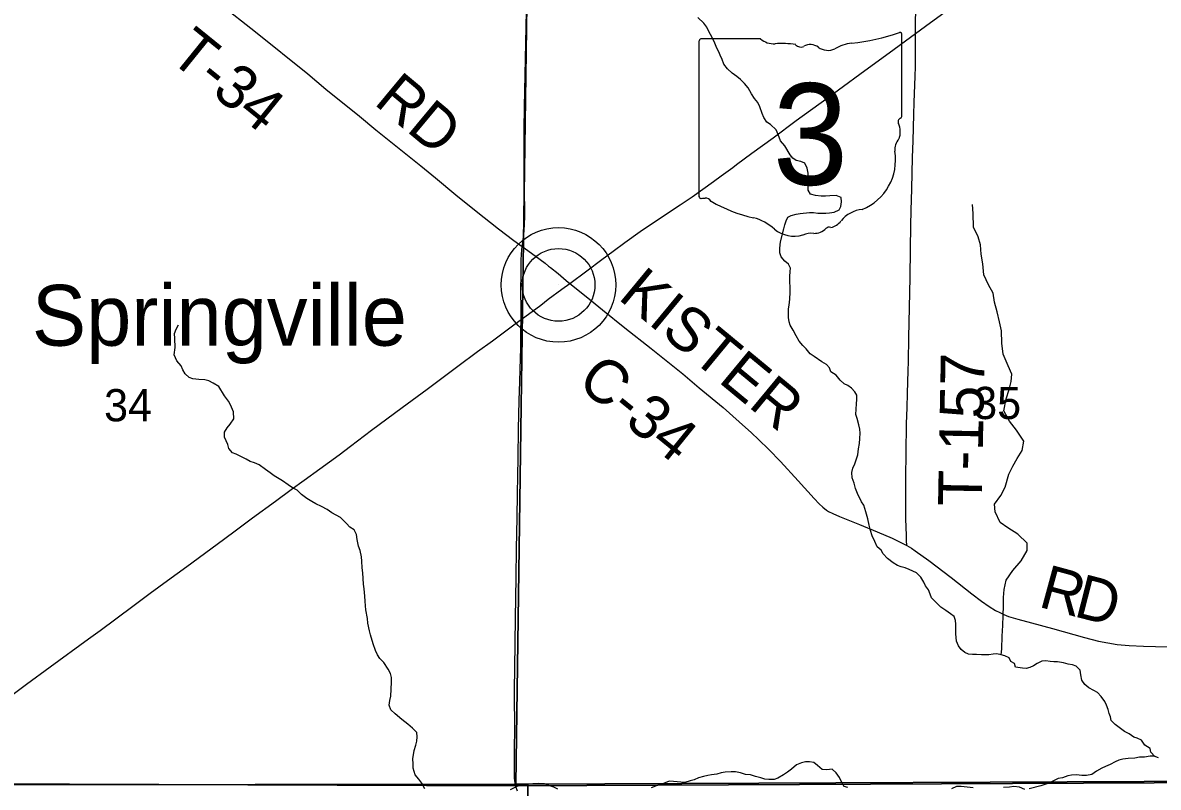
# Model space of a CAD drawing. Extents: x 0 to 34, y 0 to 22.
# Drawn here: x 2.961 to 4.435, y 15.868 to 16.861 of the extents above; entities that cross this region are included whole.
import ezdxf

# ---------------------------------------------------------------- set-up
doc = ezdxf.new("R2010")
doc.units = 0
for name, color, linetype in [('GM_X_County_Road', 7, 'Continuous'), ('GM_X_County_Road_Text', 7, 'Continuous'), ('GM_X_Minor_River', 7, 'Continuous'), ('GM_X_Section', 7, 'Continuous'), ('GM_X_Section_Text', 7, 'Continuous'), ('GM_X_State_Location', 7, 'Continuous'), ('GM_X_State_Route', 7, 'Continuous'), ('GM_X_State_Shield', 7, 'Continuous'), ('GM_X_Township_Road', 7, 'Continuous'), ('GM_X_Township_Road_Text', 7, 'Continuous'), ('GM_X_Unincorporated', 7, 'Continuous'), ('GM_X_Unincorporated_Location', 7, 'Continuous'), ('GM_X_Unincorporated_Text', 7, 'Continuous')]:
    doc.layers.add(name, color=color, linetype=linetype)

msp = doc.modelspace()

# ---------------------------------------------------------------- linework, layer by layer
at = {"layer": 'GM_X_County_Road'}
for points in [[(4.1202, 16.8475), (4.1206, 16.8925)], [(3.6712, 16.5229), (3.6752, 16.5197), (3.6994, 16.5003), (3.7139, 16.4886), (3.7428, 16.4651), (3.777, 16.4382), (3.7987, 16.4209), (3.8179, 16.4053), (3.8394, 16.3874), (3.8703, 16.3616), (3.8912, 16.3431), (3.9074, 16.3286), (3.9165, 16.3201), (3.9297, 16.3071), (3.9448, 16.2915), (3.968, 16.2665), (3.9887, 16.2433), (3.995, 16.2364), (3.9997, 16.2322), (4.0047, 16.2284), (4.0073, 16.2267), (4.0129, 16.2238), (4.0214, 16.22), (4.0473, 16.2095), (4.0703, 16.2003), (4.0898, 16.1918), (4.0949, 16.1895), (4.101, 16.1864), (4.108, 16.1827), (4.109, 16.1822)], [(4.109, 16.1822), (4.1148, 16.179), (4.1199, 16.1755), (4.1373, 16.1631), (4.1666, 16.1407), (4.1935, 16.1197), (4.2058, 16.1102), (4.2159, 16.103), (4.2239, 16.0981), (4.2295, 16.0952), (4.2351, 16.0926), (4.241, 16.0904), (4.2529, 16.0868), (4.2709, 16.0819), (4.2979, 16.0748), (4.3398, 16.0631), (4.3578, 16.0583), (4.37, 16.0558), (4.3823, 16.054), (4.3978, 16.0526), (4.4165, 16.0517), (4.4476, 16.0509)]]:
    msp.add_lwpolyline(points, dxfattribs=at)
at = {"layer": 'GM_X_Minor_River'}
for points in [[(3.8691, 16.8135), (3.8665, 16.8192), (3.8649, 16.8237), (3.8622, 16.8283), (3.8595, 16.8348), (3.8561, 16.8424), (3.8519, 16.85), (3.8492, 16.8557), (3.8454, 16.8606), (3.8373, 16.8682)], [(4.0463, 16.308), (4.0474, 16.3148), (4.0481, 16.3213), (4.0485, 16.3281), (4.0481, 16.3335), (4.0466, 16.3392), (4.0446, 16.3475), (4.0427, 16.3525), (4.0431, 16.3597), (4.0435, 16.3662), (4.0442, 16.3719), (4.0442, 16.3776), (4.0415, 16.3821), (4.0369, 16.3867), (4.0323, 16.3901), (4.0274, 16.3924), (4.0224, 16.397), (4.017, 16.4035), (4.0102, 16.408), (4.0086, 16.413), (4.0044, 16.4175), (3.9987, 16.421), (3.9884, 16.4278), (3.9834, 16.4312), (3.9784, 16.4377), (3.9738, 16.4423), (3.9692, 16.448), (3.965, 16.4548), (3.9612, 16.462), (3.9574, 16.4685), (3.9562, 16.4731), (3.9554, 16.4784), (3.9554, 16.4852), (3.9554, 16.4898), (3.9561, 16.4947), (3.9569, 16.5024), (3.9576, 16.5115), (3.9572, 16.5187), (3.9568, 16.524), (3.9568, 16.532), (3.9576, 16.5381), (3.9579, 16.5427), (3.9553, 16.548), (3.9503, 16.5518), (3.9457, 16.5575), (3.9438, 16.5624), (3.9438, 16.5685), (3.9449, 16.5769), (3.949, 16.5936), (3.9506, 16.5989), (3.9521, 16.6039), (3.9543, 16.6088), (3.9589, 16.6111), (3.965, 16.6126), (3.9704, 16.6134), (3.9826, 16.6149), (3.9875, 16.6149), (3.9933, 16.6141), (4.0039, 16.6141), (4.0085, 16.6145), (4.0146, 16.6153), (4.0211, 16.6183), (4.0234, 16.6229), (4.0241, 16.6286), (4.0237, 16.6343), (4.0172, 16.6369), (4.0089, 16.6366), (4.0035, 16.6362), (3.9978, 16.6362), (3.9902, 16.6369), (3.984, 16.6389), (3.981, 16.6438), (3.981, 16.6548), (3.9809, 16.6617), (3.9809, 16.6662), (3.9794, 16.6727), (3.9763, 16.6792), (3.9713, 16.6811), (3.9652, 16.6826), (3.9607, 16.6853), (3.9572, 16.6898), (3.9507, 16.7016), (3.945, 16.7081), (3.9419, 16.7164), (3.9392, 16.7222), (3.9319, 16.729), (3.9273, 16.7321), (3.9231, 16.7381), (3.9212, 16.7435), (3.9181, 16.7522), (3.9154, 16.7579), (3.9109, 16.7629), (3.9074, 16.7689), (3.9028, 16.7769), (3.8982, 16.7823), (3.8929, 16.7876), (3.8883, 16.7914), (3.8822, 16.796), (3.876, 16.8017), (3.8714, 16.8074), (3.8691, 16.8135)], [(4.2314, 16.0406), (4.2325, 16.0484), (4.2329, 16.0647), (4.2336, 16.0784), (4.2339, 16.0917), (4.2346, 16.1042), (4.2346, 16.1148), (4.2353, 16.1251), (4.2379, 16.1376), (4.2466, 16.1498), (4.2575, 16.1627), (4.2654, 16.176), (4.2654, 16.1855), (4.2532, 16.1972), (4.2403, 16.2052), (4.23, 16.2123), (4.2235, 16.226), (4.2227, 16.2359), (4.231, 16.2473), (4.2367, 16.2583), (4.2415, 16.275), (4.2464, 16.2853), (4.2524, 16.2955), (4.2588, 16.3058), (4.2607, 16.318), (4.2512, 16.3324), (4.2424, 16.3441), (4.2348, 16.3573), (4.2381, 16.3729), (4.2419, 16.3851), (4.2445, 16.3953), (4.2452, 16.4048), (4.2406, 16.4158), (4.2341, 16.431), (4.2325, 16.445), (4.2317, 16.4613), (4.2294, 16.4727), (4.2263, 16.486), (4.2229, 16.4985), (4.2209, 16.5103), (4.2152, 16.5209), (4.2091, 16.5341), (4.2075, 16.5482), (4.2056, 16.5607), (4.2044, 16.5728), (4.2017, 16.5831), (4.1956, 16.5959), (4.1952, 16.6138), (4.194, 16.6255)], [(3.469, 15.9163), (3.4713, 15.9231), (3.4724, 15.9284), (3.4732, 15.9338), (3.4724, 15.9395), (3.4671, 15.9452), (3.4609, 15.9505), (3.4529, 15.9566), (3.4445, 15.9638), (3.4388, 15.9691), (3.4368, 15.9752), (3.4376, 15.9809), (3.4387, 15.9866), (3.4398, 16.0049), (3.4398, 16.011), (3.4383, 16.0163), (3.4352, 16.0216), (3.4295, 16.0304), (3.4245, 16.0357), (3.4214, 16.0406), (3.4187, 16.046), (3.4157, 16.0547), (3.4126, 16.0665), (3.411, 16.0718), (3.4091, 16.0817), (3.4083, 16.0874), (3.4064, 16.0988), (3.406, 16.1041), (3.4056, 16.1102), (3.4052, 16.1167), (3.404, 16.1262), (3.4033, 16.1323), (3.4025, 16.1467), (3.4017, 16.1536), (3.4013, 16.1619), (3.4005, 16.1677), (3.399, 16.176), (3.3967, 16.1817), (3.3951, 16.1901), (3.3943, 16.1969), (3.3913, 16.2026), (3.3855, 16.2061), (3.3813, 16.211), (3.3733, 16.2186), (3.3679, 16.222), (3.3622, 16.2247), (3.3561, 16.2293), (3.3488, 16.2331), (3.3412, 16.2365), (3.3362, 16.2396), (3.3297, 16.2434), (3.3228, 16.2487), (3.3171, 16.2544), (3.311, 16.2574), (3.3053, 16.2612), (3.298, 16.2666), (3.2873, 16.2727), (3.2819, 16.2769), (3.2762, 16.281), (3.2678, 16.2871), (3.2617, 16.2898), (3.256, 16.2913), (3.251, 16.2944), (3.238, 16.3012), (3.233, 16.3027), (3.2284, 16.3084), (3.2269, 16.3138), (3.2227, 16.3233), (3.2227, 16.3294), (3.2261, 16.3351), (3.2303, 16.34), (3.2348, 16.3468), (3.2344, 16.356), (3.2306, 16.3651), (3.2279, 16.37), (3.2229, 16.3769), (3.2153, 16.3891), (3.208, 16.3933), (3.2023, 16.3963), (3.1973, 16.3974), (3.1893, 16.3982), (3.1817, 16.399), (3.1767, 16.4005), (3.1717, 16.4054), (3.1687, 16.4104), (3.1664, 16.4157), (3.161, 16.4222), (3.1575, 16.4302), (3.1587, 16.4397), (3.1583, 16.4511), (3.1579, 16.4579), (3.1598, 16.4633), (3.1632, 16.469)], [(4.4309, 15.9085), (4.4258, 15.9138), (4.425, 15.9188), (4.4181, 15.9233), (4.4139, 15.9294), (4.4082, 15.9321), (4.4036, 15.9336), (4.3975, 15.9378), (4.3914, 15.9408), (4.3845, 15.9462), (4.3795, 15.95), (4.3745, 15.9553), (4.3734, 15.9599), (4.3715, 15.9644), (4.3703, 15.9694), (4.3684, 15.9751), (4.3661, 15.9796), (4.3611, 15.9861), (4.3565, 15.9914), (4.3516, 15.9941), (4.3454, 15.9975), (4.3401, 16.0017), (4.3363, 16.0074), (4.3347, 16.0146), (4.3339, 16.0204), (4.329, 16.0257), (4.324, 16.0276), (4.3183, 16.0283), (4.3125, 16.0299), (4.3045, 16.0314), (4.2999, 16.0314), (4.295, 16.0318), (4.2893, 16.0325), (4.2843, 16.0322), (4.2782, 16.0291), (4.2736, 16.0261), (4.2687, 16.0238), (4.2641, 16.0227), (4.2591, 16.0231), (4.25, 16.0246), (4.2488, 16.0291), (4.2442, 16.0318), (4.2419, 16.0364), (4.2362, 16.039), (4.2316, 16.0406), (4.2259, 16.0417), (4.2209, 16.0413), (4.2156, 16.0406), (4.2106, 16.0402), (4.206, 16.0402), (4.1992, 16.041), (4.1942, 16.041), (4.1892, 16.0413), (4.1843, 16.0433), (4.1797, 16.0474), (4.1762, 16.052), (4.1736, 16.0581), (4.1728, 16.063), (4.1724, 16.0676), (4.1724, 16.0741), (4.1724, 16.0801), (4.172, 16.0851), (4.1704, 16.09), (4.1658, 16.0938), (4.1597, 16.098), (4.1532, 16.1022), (4.141, 16.1144), (4.1391, 16.1193), (4.1372, 16.1247), (4.1333, 16.13), (4.131, 16.1349), (4.1272, 16.1414), (4.1215, 16.1471), (4.1169, 16.149), (4.1119, 16.1513), (4.1066, 16.1536), (4.1016, 16.1547), (4.0966, 16.1566), (4.0913, 16.16), (4.084, 16.1657), (4.0783, 16.1715), (4.0756, 16.1764), (4.0706, 16.1806), (4.0675, 16.1878), (4.0641, 16.195), (4.0618, 16.2019), (4.0602, 16.2087), (4.0583, 16.2171), (4.0556, 16.2262), (4.0529, 16.2346), (4.0502, 16.2392), (4.0449, 16.2498), (4.0422, 16.2563), (4.0407, 16.2635), (4.038, 16.2703), (4.0376, 16.2772), (4.0387, 16.2829), (4.0414, 16.2886), (4.0436, 16.2951), (4.0451, 16.3), (4.0463, 16.308)], [(3.4829, 15.8664), (3.4791, 15.8737), (3.4752, 15.879), (3.4703, 15.8847), (3.4679, 15.8934), (3.4679, 15.8988), (3.4675, 15.9052), (3.469, 15.9163)], [(4.0324, 15.868), (4.0275, 15.8696), (4.024, 15.8756), (4.0213, 15.8813), (4.0171, 15.8871), (4.0121, 15.892), (4.0049, 15.8909), (3.9988, 15.8916), (3.9931, 15.8966), (3.9881, 15.9004), (3.9827, 15.9015), (3.9774, 15.9015), (3.9721, 15.9), (3.9656, 15.8974), (3.9591, 15.892), (3.9541, 15.8882), (3.9488, 15.8844), (3.9416, 15.8803), (3.9366, 15.8787), (3.9297, 15.8784), (3.9244, 15.8791), (3.9194, 15.8806), (3.9122, 15.8822), (3.9057, 15.8845), (3.8992, 15.8852), (3.8931, 15.8871), (3.8866, 15.8883), (3.8809, 15.8883), (3.8729, 15.8879), (3.8679, 15.8871), (3.8622, 15.8856), (3.8553, 15.8845), (3.8504, 15.8837), (3.845, 15.8822), (3.8385, 15.8807), (3.8328, 15.878), (3.8275, 15.8769), (3.8206, 15.8746), (3.8153, 15.875), (3.8061, 15.8761), (3.8004, 15.8765), (3.7928, 15.8731), (3.7847, 15.8705), (3.7771, 15.8678)], [(4.4357, 15.9066), (4.43, 15.9089), (4.425, 15.9089), (4.4178, 15.9077), (4.4109, 15.9074), (4.4052, 15.9062), (4.3964, 15.9059), (4.3895, 15.9051), (4.3842, 15.9036), (4.3793, 15.9013), (4.3732, 15.8979), (4.3671, 15.8952), (4.3621, 15.8933), (4.3552, 15.8895), (4.3491, 15.885), (4.3423, 15.8838), (4.3362, 15.8835), (4.3293, 15.8846), (4.3228, 15.8842), (4.3179, 15.8831), (4.311, 15.8808), (4.3053, 15.8797), (4.2969, 15.8755), (4.2908, 15.8728), (4.2828, 15.8702), (4.2679, 15.8664)], [(3.6558, 15.866), (3.6504, 15.8686), (3.6439, 15.8705), (3.6382, 15.8728), (3.6302, 15.8732), (3.6233, 15.8728), (3.6145, 15.8721), (3.6092, 15.8713), (3.6023, 15.8694), (3.5939, 15.8649)], [(4.195, 15.8676), (4.1874, 15.8687), (4.1797, 15.8695), (4.1736, 15.8695), (4.1668, 15.8664)], [(4.2622, 15.8656), (4.2553, 15.8687), (4.2477, 15.8694), (4.2423, 15.8687), (4.2343, 15.8683)]]:
    msp.add_lwpolyline(points, dxfattribs=at)
at = {"layer": 'GM_X_Section'}
for points in [[(2.5888, 16.8843), (3.6155, 16.8848), (3.6011, 15.8725), (2.5857, 15.8713)], [(3.6155, 16.8848), (4.6282, 16.8848), (4.6171, 15.8766), (3.6166, 15.8725), (3.6011, 15.8725)], [(3.6011, 15.8725), (3.6166, 15.8725), (3.6188, 14.8751), (2.6012, 14.88), (2.5857, 15.8713)], [(3.6166, 15.8725), (4.6171, 15.8766), (4.6247, 14.8633), (4.1707, 14.8603), (3.6188, 14.8751)]]:
    msp.add_lwpolyline(points, close=True, dxfattribs=at)
at = {"layer": 'GM_X_State_Route'}
for points in [[(2.1, 20.9), (2.1, 15.8695), (2.5819, 15.8726), (2.7891, 15.8734), (3.6011, 15.8701), (4.6144, 15.8751)], [(2.931, 15.9768), (2.9657, 16.0025), (2.9965, 16.0249), (3.0463, 16.0612), (3.0613, 16.0722), (3.1036, 16.1037), (3.1262, 16.1203), (3.1487, 16.1368), (3.1738, 16.1552), (3.2214, 16.19), (3.2383, 16.2029), (3.2593, 16.2184), (3.2891, 16.2398), (3.3095, 16.2551), (3.3264, 16.2673), (3.3466, 16.2819), (3.3715, 16.3003), (3.3863, 16.3116), (3.4138, 16.332), (3.4537, 16.3616), (3.4862, 16.3856), (3.5258, 16.4152), (3.5515, 16.4343), (3.5707, 16.4484), (3.6001, 16.4704), (3.6079, 16.4761), (3.6334, 16.4947), (3.6433, 16.5022), (3.6607, 16.5152), (3.6712, 16.5229), (3.6932, 16.539), (3.7128, 16.5538), (3.7276, 16.5646), (3.7427, 16.576), (3.7626, 16.5903), (3.793, 16.6105), (3.8147, 16.6247), (3.83, 16.6352), (3.8577, 16.6551), (3.8678, 16.6625), (3.8828, 16.6735), (3.8878, 16.6772), (3.9078, 16.6919), (3.9353, 16.7121), (3.9654, 16.7342), (4.0055, 16.7635), (4.0478, 16.7945), (4.0925, 16.8272), (4.1139, 16.8428), (4.1202, 16.8475), (4.1333, 16.8569), (4.1635, 16.8788)], [(4.6144, 15.8751), (3.6011, 15.8701), (2.7891, 15.8734), (2.5819, 15.8726), (2.1, 15.8695), (2.1, 14.1), (5.6455, 14.1)]]:
    msp.add_lwpolyline(points, dxfattribs=at)
at = {"layer": 'GM_X_State_Shield'}
for p, q in [((4.1026, 16.7406), (4.1026, 16.8453)), ((3.839, 16.8369), (3.839, 16.6368)), ((3.9188, 16.8403), (3.8416, 16.8403)), ((4.1026, 16.7406), (4.1026, 16.7406))]:
    msp.add_line(p, q, dxfattribs=at)
for centre, radius, start, end in [((4.0087, 17.1131), 0.2796, 275.8445, 288.9065), ((4.0997, 16.8457), 0.00294, 351.8621, 97.738), ((3.842, 16.8373), 0.00305, 98.1301, 188.1301), ((3.9372, 16.8635), 0.0296, 231.6195, 271.1119), ((3.947, 16.728), 0.1064, 80.4867, 94.9883), ((3.9711, 16.8383), 0.00855, 219.7921, 297.1024), ((3.9837, 16.8152), 0.0178, 54.4667, 119.1411), ((4.0066, 16.8469), 0.0214, 233.8562, 294.8282), ((4.0444, 16.7792), 0.0563, 97.3462, 120.7689), ((4.0995, 16.7402), 0.00314, 289.6038, 7.7341), ((4.102, 16.7329), 0.00454, 107.944, 210.337), ((4.0731, 16.7197), 0.0273, 340.033, 23.6496), ((4.1131, 16.6968), 0.0198, 136.8065, 186.9296), ((4.0244, 16.6835), 0.0699, 292.3089, 8.9858), ((3.842, 16.6363), 0.00308, 171.9584, 258.3066), ((3.8425, 16.6568), 0.0235, 267.339, 280.6039), ((3.8473, 16.6252), 0.00848, 29.7484, 93.2717), ((3.9544, 16.805), 0.2019, 240.4129, 257.1985), ((3.8942, 16.5468), 0.0632, 47.1842, 75.836), ((4.0539, 16.5806), 0.0383, 94.4031, 142.5768), ((3.9625, 16.6242), 0.0401, 230.7004, 286.2918), ((3.9886, 16.6092), 0.0214, 268.777, 315.5493), ((4.0079, 16.5898), 0.00601, 65.7517, 132.6484), ((4.0053, 16.6174), 0.0226, 282.8732, 323.2771), ((3.9856, 16.555), 0.0329, 85.6951, 111.2099)]:
    msp.add_arc(centre, radius, start, end, dxfattribs=at)
at = {"layer": 'GM_X_Township_Road'}
for points in [[(3.2169, 16.886), (3.2629, 16.8494), (3.3308, 16.7948), (3.3544, 16.7751), (3.3981, 16.74), (3.4195, 16.7221), (3.4776, 16.6756), (3.4969, 16.6599), (3.5233, 16.638), (3.5496, 16.6166), (3.5787, 16.5938), (3.5987, 16.5784), (3.6094, 16.5707)], [(3.6094, 16.5707), (3.6101, 16.5755), (3.6119, 16.5909), (3.6126, 16.6002), (3.6129, 16.6095), (3.6128, 16.6219), (3.6123, 16.6374), (3.6119, 16.6654), (3.6119, 16.7039), (3.612, 16.7225), (3.6126, 16.7523), (3.6138, 16.8144), (3.6152, 16.8765)], [(4.109, 16.1822), (4.1087, 16.1891), (4.1084, 16.1953), (4.1077, 16.2171), (4.1077, 16.2544), (4.1078, 16.2731), (4.1079, 16.3007), (4.1082, 16.3161), (4.1084, 16.3267), (4.1087, 16.3407), (4.1094, 16.3614), (4.11, 16.3802), (4.1108, 16.4092), (4.111, 16.4216), (4.1117, 16.4527), (4.1131, 16.5306), (4.1135, 16.5672), (4.1143, 16.5982), (4.1146, 16.6174), (4.1155, 16.6457), (4.1164, 16.6862), (4.1171, 16.7079), (4.1181, 16.7422), (4.1186, 16.7577), (4.1198, 16.7919), (4.1201, 16.8043), (4.1203, 16.8249), (4.1201, 16.8355), (4.1202, 16.8475)], [(3.6079, 16.4761), (3.6079, 16.4919), (3.6077, 16.5105), (3.6079, 16.5384), (3.608, 16.5539), (3.6083, 16.5601), (3.6088, 16.5663), (3.6094, 16.5707)], [(3.6094, 16.5707), (3.6138, 16.5676), (3.6264, 16.5586), (3.6392, 16.549), (3.6436, 16.5454), (3.646, 16.5435), (3.656, 16.5357), (3.6666, 16.5267), (3.6712, 16.5229)], [(3.6712, 16.5229), (3.6752, 16.5197), (3.6994, 16.5003), (3.7139, 16.4886), (3.7428, 16.4651), (3.777, 16.4382), (3.7987, 16.4209), (3.8179, 16.4053), (3.8394, 16.3874), (3.8703, 16.3616), (3.8912, 16.3431), (3.9074, 16.3286), (3.9165, 16.3201), (3.9297, 16.3071), (3.9448, 16.2915), (3.968, 16.2665), (3.9887, 16.2433), (3.995, 16.2364), (3.9997, 16.2322), (4.0047, 16.2284), (4.0073, 16.2267), (4.0129, 16.2238), (4.0214, 16.22), (4.0473, 16.2095), (4.0703, 16.2003), (4.0898, 16.1918), (4.0949, 16.1895), (4.101, 16.1864), (4.108, 16.1827), (4.109, 16.1822)], [(3.6013, 15.8696), (3.6004, 15.8741), (3.5996, 15.8803), (3.5992, 15.8896), (3.5995, 15.9081), (3.5996, 15.9143), (3.5996, 15.9236), (3.5997, 15.9391), (3.5994, 15.995), (3.5997, 16.023), (3.6008, 16.0882), (3.6017, 16.141), (3.6021, 16.1783), (3.6027, 16.2187), (3.6032, 16.2497), (3.604, 16.2963), (3.6048, 16.3336), (3.6056, 16.3708), (3.6063, 16.3956), (3.6067, 16.4112), (3.6077, 16.4391), (3.6078, 16.4609), (3.6079, 16.4761)], [(4.109, 16.1822), (4.1148, 16.179), (4.1199, 16.1755), (4.1373, 16.1631), (4.1666, 16.1407), (4.1935, 16.1197), (4.2058, 16.1102), (4.2159, 16.103), (4.2239, 16.0981), (4.2295, 16.0952), (4.2351, 16.0926), (4.241, 16.0904), (4.2529, 16.0868), (4.2709, 16.0819), (4.2979, 16.0748), (4.3398, 16.0631), (4.3578, 16.0583), (4.37, 16.0558), (4.3823, 16.054), (4.3978, 16.0526), (4.4165, 16.0517), (4.4476, 16.0509)], [(3.6033, 15.8634), (3.6013, 15.8696)]]:
    msp.add_lwpolyline(points, dxfattribs=at)
at = {"layer": 'GM_X_Unincorporated'}
for radius in [0.0744, 0.0472]:
    msp.add_circle((3.6566, 16.5209), radius, dxfattribs=at)
at = {"layer": 'GM_X_Unincorporated_Location'}
msp.add_line((3.6566, 16.5209), (3.6566, 16.5209), dxfattribs=at)

# ---------------------------------------------------------------- texts
at = {"layer": 'GM_X_County_Road_Text'}
for s, height, rotation, p in [('KISTER', 0.05682, 320.3929, (3.7325, 16.5035)), ('C-34', 0.05682, 320.9237, (3.6786, 16.3912)), ('R', 0.0568, 344.7757, (4.2783, 16.1033)), ('D', 0.0568, 345.669, (4.3242, 16.0908))]:
    msp.add_text(s, height=height, rotation=rotation, dxfattribs=at).set_placement(p)
at = {"layer": 'GM_X_Section_Text'}
for s, p in [('34', (3.0664, 16.3437)), ('35', (4.1951, 16.3466))]:
    msp.add_text(s, height=0.04186, rotation=0, dxfattribs=at).set_placement(p)
at = {"layer": 'GM_X_State_Location'}
msp.add_text('3', height=0.000189, rotation=0, dxfattribs=at).set_placement((3.9393, 16.7097))
for s in ['s', 'r']:
    msp.add_text(s, height=0.000189, dxfattribs=at).set_placement((3.9678, 16.7235))
at = {"layer": 'GM_X_State_Shield'}
msp.add_text('3', height=0.1318, dxfattribs=at).set_placement((3.9347, 16.6509))
at = {"layer": 'GM_X_Township_Road_Text'}
for s, rotation, p in [('T-34', 321.0091, (3.1489, 16.8145)), ('RD', 320.2575, (3.4153, 16.7566)), ('T-157', 88.9101, (4.2062, 16.2333))]:
    msp.add_text(s, height=0.05682, rotation=rotation, dxfattribs=at).set_placement(p)
at = {"layer": 'GM_X_Unincorporated_Text'}
msp.add_text('Springville', height=0.078977, rotation=0, dxfattribs=at).set_placement((2.9726, 16.4419))

doc.saveas('drawing.dxf')
